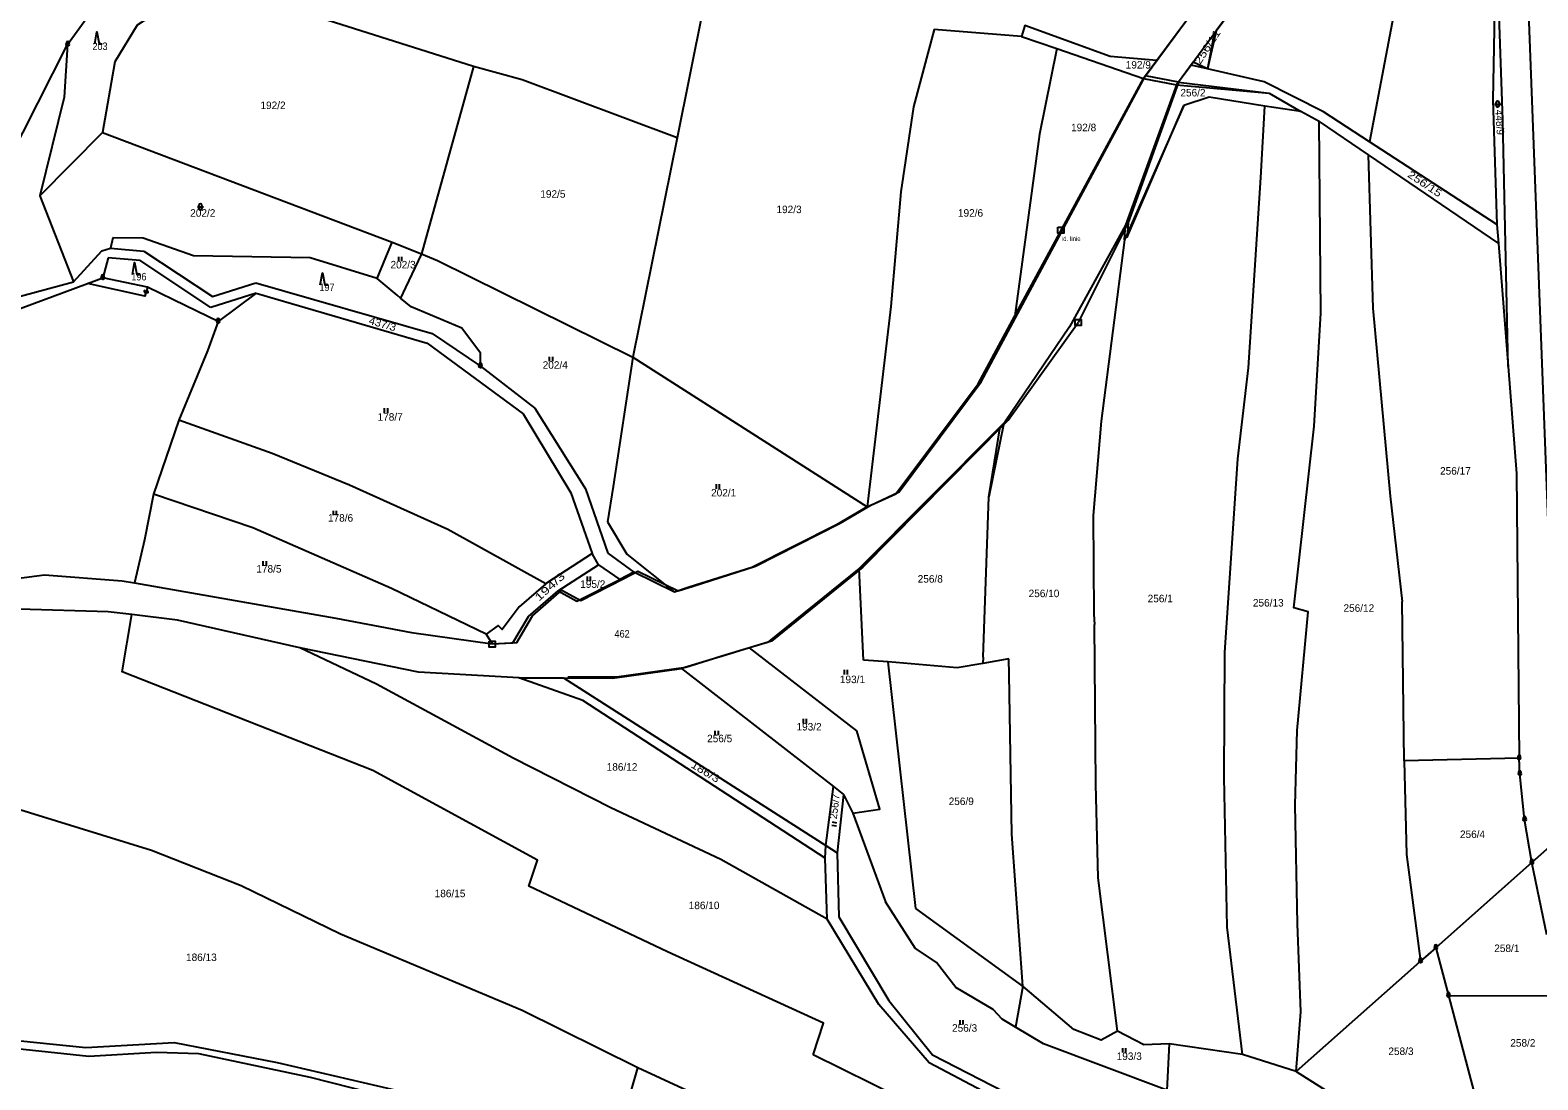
# Model space of a CAD drawing. Extents: x -680102 to -677253, y -1007548 to -1006096.
# Drawn here: x -678783 to -678281, y -1006966 to -1006617 of the extents above; entities that cross this region are included whole.
import ezdxf

# ---------------------------------------------------------------- set-up
doc = ezdxf.new("R2010")
doc.units = 0
for name, color, linetype, lineweight in [('1', 7, 'Continuous', 25), ('11', 7, 'Continuous', 25), ('24', 7, 'Continuous', 25), ('25', 7, 'Continuous', 25), ('35', 7, 'Continuous', 25), ('4', 7, 'Continuous', 25)]:
    doc.layers.add(name, color=color, linetype=linetype, lineweight=lineweight)
doc.layers.add('18', color=7, linetype='Continuous')

msp = doc.modelspace()

# ---------------------------------------------------------------- linework, layer by layer
at = {"layer": '1'}
for p, q in [((-678292.98, -1006647), (-678295.16, -1006581.68)), ((-678327.99, -1006605.23), (-678337.28, -1006654.25)), ((-678284.39, -1006611.4), (-678278.02, -1006780.4)), ((-678389.05, -1006618.29), (-678391.25, -1006629.93)), ((-678408.13, -1006627.15), (-678423.65, -1006625.83)), ((-678635.56, -1006629.14), (-678652.93, -1006691.54)), ((-678412.57, -1006633.12), (-678401.62, -1006635.25)), ((-678396.74, -1006628.67), (-678401.62, -1006635.25)), ((-678401.62, -1006635.25), (-678418.52, -1006681.96)), ((-678401.62, -1006635.25), (-678370.74, -1006638.02)), ((-678352.67, -1006644.27), (-678372.38, -1006634.27)), ((-678370.74, -1006638.02), (-678360.18, -1006644.19)), ((-678399.16, -1006642.13), (-678418.89, -1006686.84)), ((-678390.75, -1006639.42), (-678399.16, -1006642.13)), ((-678296.26, -1006640.29), (-678294.91, -1006681.72)), ((-678291.19, -1006729.01), (-678292.98, -1006647)), ((-678337.76, -1006658.53), (-678336.21, -1006709.63)), ((-678418.52, -1006681.96), (-678437.25, -1006715.74)), ((-678418.89, -1006686.84), (-678418.52, -1006681.96)), ((-678294.91, -1006681.72), (-678294.43, -1006688.11)), ((-678755.69, -1006686.13), (-678756.46, -1006689.57)), ((-678745.51, -1006686.29), (-678755.69, -1006686.13)), ((-678728.77, -1006692.22), (-678745.51, -1006686.29)), ((-678667.68, -1006699.66), (-678662.64, -1006687.58)), ((-678294.43, -1006688.11), (-678291.19, -1006729.01)), ((-678759.35, -1006690.53), (-678756.46, -1006689.57)), ((-678757.22, -1006692.78), (-678759.02, -1006699.49)), ((-678746.58, -1006693.69), (-678757.22, -1006692.78)), ((-678756.46, -1006689.57), (-678745.28, -1006690.57)), ((-678689.97, -1006692.83), (-678728.77, -1006692.22)), ((-678652.93, -1006691.54), (-678658.18, -1006702.66)), ((-678723.02, -1006709.32), (-678746.58, -1006693.69)), ((-678647.53, -1006693.75), (-678582.53, -1006725.83)), ((-678764.08, -1006701.41), (-678759.02, -1006699.49)), ((-678744.09, -1006702.62), (-678759.02, -1006699.49)), ((-678708.02, -1006701.1), (-678649.31, -1006718.06)), ((-678658.18, -1006702.66), (-678659.91, -1006706.22)), ((-678707.98, -1006704.58), (-678723.02, -1006709.32)), ((-678707.98, -1006704.58), (-678720.62, -1006714.05)), ((-678659.91, -1006706.22), (-678661.01, -1006705.29)), ((-678656.39, -1006709.18), (-678659.91, -1006706.22)), ((-678639.46, -1006716.2), (-678656.39, -1006709.18)), ((-678336.21, -1006709.63), (-678330.47, -1006772.13)), ((-678720.62, -1006714.05), (-678724.17, -1006723.76)), ((-678649.31, -1006718.06), (-678633.3, -1006728.9)), ((-678437.25, -1006715.74), (-678458.76, -1006747.53)), ((-678724.17, -1006723.76), (-678733.69, -1006746.86)), ((-678582.53, -1006725.83), (-678504.57, -1006775.64)), ((-678291.19, -1006729.01), (-678288.37, -1006764.62)), ((-678619.06, -1006744.74), (-678603.23, -1006770.99)), ((-678288.37, -1006764.62), (-678287.5, -1006859.31)), ((-678742.09, -1006771.5), (-678745.09, -1006786.69)), ((-678709.07, -1006782.71), (-678742.09, -1006771.5)), ((-678603.23, -1006770.99), (-678596.1, -1006791.26)), ((-678598.31, -1006769.67), (-678590.92, -1006791.09)), ((-678330.47, -1006772.13), (-678326.43, -1006807.17)), ((-678504.57, -1006775.64), (-678514.78, -1006781.69)), ((-678611.57, -1006801.32), (-678644.09, -1006783.19)), ((-678514.78, -1006781.69), (-678542.93, -1006795.87)), ((-678745.09, -1006786.69), (-678748.44, -1006800.99)), ((-678590.92, -1006791.09), (-678582.19, -1006797.41)), ((-678809.39, -1006802.43), (-678778.41, -1006798.31)), ((-678778.41, -1006798.31), (-678752.56, -1006800.28)), ((-678594.01, -1006794.95), (-678586.85, -1006799.87)), ((-678582.19, -1006797.41), (-678586.85, -1006799.87)), ((-678568.69, -1006804.03), (-678582.19, -1006797.41)), ((-678507.21, -1006796.26), (-678537.78, -1006820.79)), ((-678325.76, -1006860.25), (-678326.43, -1006807.17)), ((-678693.35, -1006822.57), (-678734.16, -1006813.39)), ((-678429.05, -1006811.35), (-678428.88, -1006814.85)), ((-678557.11, -1006826.67), (-678566.3, -1006829.46)), ((-678552.9, -1006825.39), (-678557.11, -1006826.67)), ((-678474.56, -1006829.3), (-678497.6, -1006827.29)), ((-678465.97, -1006825.71), (-678466.07, -1006827.77)), ((-678589.32, -1006832.67), (-678566.3, -1006829.46)), ((-678518.29, -1006888.42), (-678515.73, -1006868.76)), ((-678512.38, -1006871.37), (-678514.5, -1006890.81)), ((-678283.27, -1006894.09), (-678285.7, -1006879.74)), ((-678518.51, -1006892.56), (-678518.29, -1006888.42)), ((-678452.68, -1006935.19), (-678456.35, -1006884.57)), ((-678325.05, -1006891.38), (-678320.34, -1006926.92)), ((-678278.33, -1006918.05), (-678283.27, -1006894.09)), ((-678322.71, -1006929.01), (-678361.71, -1006963.54)), ((-678320.34, -1006926.92), (-678322.71, -1006929.01)), ((-678452.68, -1006935.19), (-678455.22, -1006948.82)), ((-678311.06, -1006938.3), (-678272.94, -1006938.41)), ((-678580.87, -1006962.32), (-678619.34, -1006943.25)), ((-678589.4, -1006991.58), (-678580.87, -1006962.32)), ((-678361.71, -1006963.54), (-678344.26, -1006974.65))]:
    msp.add_line(p, q, dxfattribs=at)
for points in [[(-678294.65, -1006573.35), (-678295.16, -1006581.68), (-678296.26, -1006640.29)], [(-678770.69, -1006621.83), (-678757.37, -1006603.24), (-678741.78, -1006591.66)], [(-678382.03, -1006592), (-678408.13, -1006627.15), (-678412.57, -1006633.12)], [(-678723.77, -1006599.91), (-678747.58, -1006615.43), (-678754.95, -1006627.57), (-678759.08, -1006651.17)], [(-678567.8, -1006652.87), (-678619.4, -1006633.56), (-678635.56, -1006629.14), (-678690.66, -1006611.71), (-678723.77, -1006599.91)], [(-678378.6, -1006604.2), (-678389.05, -1006618.29), (-678396.74, -1006628.67)], [(-678559.23, -1006610.41), (-678567.8, -1006652.87), (-678582.53, -1006725.83)], [(-678453.19, -1006619.16), (-678482.29, -1006616.83), (-678489.11, -1006642.57), (-678493.38, -1006670.87), (-678496.7, -1006709.02), (-678504.57, -1006775.64)], [(-678423.65, -1006625.83), (-678452.11, -1006615.47), (-678453.19, -1006619.16)], [(-678825.3, -1006702.25), (-678795.52, -1006670.55), (-678770.69, -1006621.83), (-678771.83, -1006639.32), (-678780, -1006672.18), (-678768.75, -1006700.87)], [(-678453.19, -1006619.16), (-678441.4, -1006623.21), (-678412.57, -1006633.12)], [(-678441.4, -1006623.21), (-678447.23, -1006651.72), (-678455.34, -1006712.11)], [(-678467.62, -1006734.78), (-678455.34, -1006712.11), (-678412.57, -1006633.12)], [(-678372.38, -1006634.27), (-678391.25, -1006629.93), (-678396.74, -1006628.67)], [(-678360.18, -1006644.19), (-678372.18, -1006642.32), (-678390.75, -1006639.42)], [(-678379.64, -1006957.94), (-678384.71, -1006915.5), (-678385.68, -1006865.59), (-678385.49, -1006824.2), (-678381.19, -1006759.69), (-678377.6, -1006729.48), (-678373.53, -1006666.09), (-678372.18, -1006642.32)], [(-678361.71, -1006963.54), (-678360.18, -1006943.72), (-678361.33, -1006914.42), (-678362.06, -1006874.92), (-678361.46, -1006850.06), (-678357.73, -1006810.61), (-678362.53, -1006809.3), (-678355.8, -1006748.81), (-678353.55, -1006711.22), (-678354.06, -1006647.41), (-678360.18, -1006644.19)], [(-678354.06, -1006647.41), (-678337.76, -1006658.53), (-678294.43, -1006688.11)], [(-678294.91, -1006681.72), (-678337.28, -1006654.25), (-678352.67, -1006644.27)], [(-678780, -1006672.18), (-678759.08, -1006651.17), (-678662.64, -1006687.58)], [(-678662.64, -1006687.58), (-678652.93, -1006691.54), (-678647.53, -1006693.75)], [(-678418.89, -1006686.84), (-678426.68, -1006747.13), (-678429.29, -1006778.6), (-678429.05, -1006811.35)], [(-678830.07, -1006706.12), (-678825.3, -1006702.25), (-678804.17, -1006710.32), (-678768.75, -1006700.87), (-678759.35, -1006690.53)], [(-678745.28, -1006690.57), (-678722.52, -1006705.7), (-678708.02, -1006701.1)], [(-678661.01, -1006705.29), (-678667.68, -1006699.66), (-678689.97, -1006692.83)], [(-678801.5, -1006712.47), (-678790.35, -1006711.15), (-678764.08, -1006701.41)], [(-678720.62, -1006714.05), (-678731.31, -1006708.84), (-678744.09, -1006702.62)], [(-678707.98, -1006704.58), (-678651.04, -1006721.27), (-678619.06, -1006744.74)], [(-678633.3, -1006728.9), (-678633.27, -1006724.57), (-678639.46, -1006716.2)], [(-678582.53, -1006725.83), (-678589.14, -1006768.88), (-678590.95, -1006780.65)], [(-678633.3, -1006728.9), (-678615.21, -1006742.84), (-678598.31, -1006769.67)], [(-678504.57, -1006775.64), (-678495.02, -1006771.31), (-678467.62, -1006734.78)], [(-678702.61, -1006757.93), (-678733.69, -1006746.86), (-678742.09, -1006771.5)], [(-678458.76, -1006747.53), (-678460.31, -1006749.09), (-678507.21, -1006796.26)], [(-678465.97, -1006825.71), (-678464.06, -1006772.32), (-678460.31, -1006749.09)], [(-678644.09, -1006783.19), (-678676.91, -1006768.49), (-678702.61, -1006757.93)], [(-678631.41, -1006818.02), (-678662.94, -1006802.85), (-678709.07, -1006782.71)], [(-678590.95, -1006780.65), (-678584.59, -1006791.47), (-678568.69, -1006804.03)], [(-678681.43, -1006812.76), (-678656.18, -1006817.5), (-678629.37, -1006821.24), (-678622.5, -1006820.98), (-678617.29, -1006812.19), (-678607.46, -1006803.61), (-678594.01, -1006794.95), (-678596.1, -1006791.26), (-678611.34, -1006801.12)], [(-678542.93, -1006795.87), (-678563.77, -1006802.47), (-678568.69, -1006804.03)], [(-678505.82, -1006826.67), (-678506.03, -1006822.05), (-678507.21, -1006796.26)], [(-678752.56, -1006800.28), (-678748.44, -1006800.99), (-678681.43, -1006812.76)], [(-678611.34, -1006801.12), (-678611.57, -1006801.32), (-678620.34, -1006808.98)], [(-678607.46, -1006803.61), (-678601.18, -1006807.05), (-678586.85, -1006799.87)], [(-678757.2, -1006810.62), (-678786.87, -1006809.74), (-678808.33, -1006812.25), (-678855.42, -1006828.22), (-678875.46, -1006840.19)], [(-678734.16, -1006813.39), (-678749.38, -1006811.56), (-678757.2, -1006810.62)], [(-678570.97, -1006923.78), (-678617.18, -1006901.88), (-678614.3, -1006893.22), (-678669.14, -1006863.38), (-678752.57, -1006830.6), (-678749.38, -1006811.56)], [(-678620.34, -1006808.98), (-678626.07, -1006816.55), (-678627.33, -1006815.14), (-678631.41, -1006818.02), (-678629.37, -1006821.24)], [(-678421.24, -1006950.19), (-678427.67, -1006899.18), (-678428.43, -1006867.92), (-678428.88, -1006814.85)], [(-678517.9, -1006912.86), (-678553.21, -1006893.09), (-678589.86, -1006875.88), (-678622.42, -1006859.28), (-678667.88, -1006834.7), (-678693.35, -1006822.57)], [(-678620.49, -1006832.57), (-678653.9, -1006830.72), (-678693.35, -1006822.57)], [(-678537.78, -1006820.79), (-678543.67, -1006822.58), (-678552.9, -1006825.39)], [(-678509.3, -1006877.66), (-678500.3, -1006876.27), (-678507.96, -1006850.17), (-678543.67, -1006822.58)], [(-678488.35, -1006909.3), (-678497.6, -1006827.29), (-678505.82, -1006826.67)], [(-678457.4, -1006826.21), (-678466.07, -1006827.77), (-678474.56, -1006829.3)], [(-678456.35, -1006884.57), (-678457.31, -1006831.43), (-678457.4, -1006826.21)], [(-678398.33, -1007005.38), (-678440.63, -1006983.55), (-678483.96, -1006960.65), (-678500.63, -1006941.25), (-678517.9, -1006912.86), (-678518.51, -1006892.56), (-678599.19, -1006840.09), (-678620.49, -1006832.57)], [(-678620.49, -1006832.57), (-678605.61, -1006832.62), (-678589.32, -1006832.67)], [(-678605.61, -1006832.62), (-678518.29, -1006888.42), (-678514.5, -1006890.81), (-678513.99, -1006912.1), (-678497.38, -1006940)], [(-678566.3, -1006829.46), (-678515.73, -1006868.76), (-678512.38, -1006871.37)], [(-678285.7, -1006879.74), (-678287.32, -1006864.53), (-678287.5, -1006859.31), (-678325.76, -1006860.25), (-678325.05, -1006891.38)], [(-678619.34, -1006943.25), (-678679.89, -1006917.85), (-678712.96, -1006901.76), (-678742.78, -1006890), (-678790.92, -1006875.17), (-678826.88, -1006865.18)], [(-678512.38, -1006871.37), (-678509.3, -1006877.66), (-678498.46, -1006907.11)], [(-678283.27, -1006894.09), (-678315.26, -1006922.42), (-678320.34, -1006926.92)], [(-678459.57, -1006946.2), (-678462.59, -1006942.93), (-678475.05, -1006935.68), (-678481.46, -1006927.33), (-678488.59, -1006922.49), (-678498.46, -1006907.11)], [(-678361.71, -1006963.54), (-678379.64, -1006957.94), (-678404.06, -1006954.43), (-678412.41, -1006954.67), (-678421.24, -1006950.19), (-678426.68, -1006953.1), (-678435.75, -1006949.59), (-678452.68, -1006935.19), (-678488.35, -1006909.3)], [(-678522.49, -1006958), (-678519.05, -1006947.54), (-678570.97, -1006923.78)], [(-678315.26, -1006922.42), (-678311.06, -1006938.3), (-678302.61, -1006970.19), (-678264.49, -1006970.3)], [(-678497.38, -1006940), (-678482.78, -1006958), (-678407.48, -1006996.76)], [(-678445.9, -1006954.43), (-678455.22, -1006948.82), (-678459.57, -1006946.2)], [(-678741.11, -1006957.27), (-678763.59, -1006958.64), (-678796.05, -1006955.12), (-678818.04, -1006953.75), (-678852.96, -1006954.87)], [(-678821.5, -1006950.78), (-678786.36, -1006953.33), (-678764.64, -1006955.64)], [(-678764.64, -1006955.64), (-678735.18, -1006953.98), (-678700.9, -1006960.54)], [(-678428.42, -1007058.52), (-678456.65, -1007048.79), (-678480.7, -1007039.81), (-678505.2, -1007028.21), (-678600.16, -1006990.16), (-678648.38, -1006976.17), (-678689.83, -1006965.56), (-678727.06, -1006957.66), (-678741.11, -1006957.27)], [(-678448.47, -1006998.31), (-678464.79, -1006989.56), (-678493.35, -1006972.45), (-678522.49, -1006958)], [(-678404.06, -1006954.43), (-678404.79, -1006969.79), (-678445.9, -1006954.43)], [(-678700.9, -1006960.54), (-678658.05, -1006970.53), (-678610.61, -1006983.2)], [(-678404.4, -1007041.11), (-678426.05, -1007034.58), (-678466.45, -1007018.51), (-678510.07, -1006995.35), (-678525.91, -1006987.79), (-678580.87, -1006962.32)]]:
    msp.add_lwpolyline(points, dxfattribs=at)
at = {"layer": '11'}
for p, q in [((-678400.89, -1006634.35), (-678370.74, -1006638.02)), ((-678417.64, -1006681.12), (-678434.3, -1006714.32)), ((-678457.66, -1006746.82), (-678434.3, -1006714.32))]:
    msp.add_line(p, q, dxfattribs=at)
for points in [[(-678282.9, -1006501.51), (-678288.96, -1006531.28), (-678290.92, -1006545.55), (-678299.42, -1006535.34), (-678316.02, -1006548.44), (-678337.35, -1006565.27), (-678377.98, -1006603.23), (-678388.38, -1006617.35), (-678391.25, -1006629.93), (-678396.04, -1006627.76), (-678400.89, -1006634.35), (-678411.85, -1006632.26)], [(-678629.37, -1006821.24), (-678621.16, -1006820.81), (-678615.98, -1006812), (-678606.18, -1006803.39), (-678599.89, -1006806.81), (-678585.58, -1006799.58), (-678580.93, -1006797.11), (-678567.41, -1006803.68), (-678562.49, -1006802.11), (-678541.67, -1006795.44), (-678513.57, -1006781.17), (-678503.38, -1006775.08), (-678493.85, -1006770.72), (-678466.57, -1006734.1), (-678454.36, -1006711.39), (-678411.85, -1006632.26), (-678407.43, -1006626.27), (-678381.45, -1006591.04), (-678371.57, -1006577.31), (-678346.7, -1006550.29), (-678328.04, -1006532.61), (-678313.38, -1006521.44), (-678323.91, -1006515.59)], [(-678400.89, -1006634.35), (-678417.64, -1006681.12), (-678417.99, -1006686), (-678399.16, -1006642.13)], [(-678459.21, -1006748.39), (-678505.95, -1006795.71), (-678536.44, -1006820.34), (-678542.33, -1006822.15), (-678551.55, -1006824.99), (-678555.75, -1006826.28), (-678564.93, -1006829.1), (-678587.94, -1006832.39), (-678604.23, -1006832.39)], [(-678457.66, -1006746.82), (-678459.21, -1006748.39), (-678464.06, -1006772.32)]]:
    msp.add_lwpolyline(points, dxfattribs=at)
at = {"layer": '24'}
for centre, radius in [((-678770.69, -1006621.83), 0.5), ((-678770.69, -1006621.83), 0.022), ((-678759.02, -1006699.49), 0.5), ((-678759.02, -1006699.49), 0.022), ((-678720.62, -1006714.05), 0.5), ((-678720.62, -1006714.05), 0.022), ((-678633.3, -1006728.9), 0.5), ((-678633.3, -1006728.9), 0.022), ((-678287.5, -1006859.31), 0.5), ((-678287.5, -1006859.31), 0.022), ((-678287.32, -1006864.53), 0.5), ((-678287.32, -1006864.53), 0.022), ((-678285.7, -1006879.74), 0.5), ((-678285.7, -1006879.74), 0.022), ((-678283.27, -1006894.09), 0.5), ((-678283.27, -1006894.09), 0.022), ((-678315.26, -1006922.42), 0.5), ((-678315.26, -1006922.42), 0.022), ((-678320.34, -1006926.92), 0.5), ((-678320.34, -1006926.92), 0.022), ((-678311.06, -1006938.3), 0.5), ((-678311.06, -1006938.3), 0.022)]:
    msp.add_circle(centre, radius, dxfattribs=at)
for centre in [(-678770.691, -1006621.267), (-678759.021, -1006698.927), (-678720.621, -1006713.487), (-678633.301, -1006728.337), (-678287.501, -1006858.747), (-678287.321, -1006863.967), (-678285.701, -1006879.177), (-678283.271, -1006893.527), (-678315.261, -1006921.857), (-678320.341, -1006926.357), (-678311.061, -1006937.737)]:
    msp.add_arc(centre, 0.437, 328.35109, 209.97456, dxfattribs=at)
at = {"layer": '25'}
for p, q in [((-678295.67, -1006641.66), (-678293.67, -1006641.66)), ((-678295.17, -1006642.16), (-678295.17, -1006641.16)), ((-678294.17, -1006641.16), (-678294.17, -1006642.16)), ((-678727.52, -1006675.87), (-678725.52, -1006675.87)), ((-678727.02, -1006676.37), (-678727.02, -1006675.37)), ((-678726.02, -1006675.37), (-678726.02, -1006676.37)), ((-678660.467, -1006693.975), (-678660.467, -1006692.475)), ((-678659.433, -1006693.975), (-678659.433, -1006692.475)), ((-678610.247, -1006727.265), (-678610.247, -1006725.765)), ((-678609.213, -1006727.265), (-678609.213, -1006725.765)), ((-678665.167, -1006744.375), (-678665.167, -1006742.875)), ((-678664.133, -1006744.375), (-678664.133, -1006742.875)), ((-678554.707, -1006769.695), (-678554.707, -1006768.195)), ((-678553.673, -1006769.695), (-678553.673, -1006768.195)), ((-678682.217, -1006778.475), (-678682.217, -1006776.975)), ((-678681.183, -1006778.475), (-678681.183, -1006776.975)), ((-678705.567, -1006795.275), (-678705.567, -1006793.775)), ((-678704.533, -1006795.275), (-678704.533, -1006793.775)), ((-678597.697, -1006800.405), (-678597.697, -1006798.905)), ((-678596.663, -1006800.405), (-678596.663, -1006798.905)), ((-678512.097, -1006831.475), (-678512.097, -1006829.975)), ((-678511.063, -1006831.475), (-678511.063, -1006829.975)), ((-678525.797, -1006847.735), (-678525.797, -1006846.235)), ((-678524.763, -1006847.735), (-678524.763, -1006846.235)), ((-678555.097, -1006851.695), (-678555.097, -1006850.195)), ((-678554.063, -1006851.695), (-678554.063, -1006850.195)), ((-678514.807, -1006881.92), (-678516.286, -1006881.67)), ((-678514.635, -1006880.902), (-678516.114, -1006880.651)), ((-678473.587, -1006947.955), (-678473.587, -1006946.455)), ((-678472.553, -1006947.955), (-678472.553, -1006946.455)), ((-678419.487, -1006957.285), (-678419.487, -1006955.785)), ((-678418.453, -1006957.285), (-678418.453, -1006955.785))]:
    msp.add_line(p, q, dxfattribs=at)
for points in [[(-678761.69, -1006621.58), (-678760.94, -1006617.58), (-678760.19, -1006621.58), (-678759.19, -1006621.58)], [(-678749.15, -1006698.43), (-678748.4, -1006694.43), (-678747.65, -1006698.43), (-678746.65, -1006698.43)], [(-678686.6, -1006701.84), (-678685.85, -1006697.84), (-678685.1, -1006701.84), (-678684.1, -1006701.84)]]:
    msp.add_lwpolyline(points, dxfattribs=at)
for centre, radius, start, end in [((-678294.67, -1006641.16), 0.5, 0.101, 180.00143), ((-678294.67, -1006642.16), 0.5, 180.10243, 0.00286), ((-678726.52, -1006675.37), 0.5, 0.101, 180.00143), ((-678726.52, -1006676.37), 0.5, 180.10243, 0.00286), ((-678744.901, -1006703.966), 0.369, 110.01057, 341.81548), ((-678744.2, -1006704.192), 0.367, 289.89097, 162.25662)]:
    msp.add_arc(centre, radius, start, end, dxfattribs=at)
at = {"layer": '35'}
for points in [[(-678441.06, -1006682.64), (-678439.06, -1006682.64), (-678439.06, -1006684.64), (-678441.06, -1006684.64)], [(-678435.3, -1006713.32), (-678433.3, -1006713.32), (-678433.3, -1006715.32), (-678435.3, -1006715.32)], [(-678630.38, -1006820.36), (-678628.38, -1006820.36), (-678628.38, -1006822.36), (-678630.38, -1006822.36)]]:
    msp.add_lwpolyline(points, close=True, dxfattribs=at)
at = {"layer": '4'}
msp.add_line((-678283.27, -1006894.09), (-678274.13, -1006885.85), dxfattribs=at)
msp.add_lwpolyline([(-678744.09, -1006702.62), (-678745, -1006705.54), (-678764.08, -1006701.41)], dxfattribs=at)

# ---------------------------------------------------------------- texts
at = {"layer": '18'}
for s, rotation, width, p in [('256/11', 57.2, 1.25, (-678393.679, -1006628.654)), ('256/15', 326.303, 1.25, (-678324.923, -1006665.705)), ('437/3', 343.903, 1.1, (-678670.643, -1006714.764)), ('194/3', 42.5, 1.45, (-678613.818, -1006807.278)), ('186/3', 328.803, 1.25, (-678563.486, -1006862.193))]:
    msp.add_text(s, height=2.5, rotation=rotation, dxfattribs=dict(at, width=width)).set_placement(p)
at = {"layer": '18', "width": 0.9}
for s, p in [('203', (-678762.43, -1006623.68)), ('196', (-678749.47, -1006700.35)), ('197', (-678686.88, -1006703.88)), ('462', (-678588.63, -1006819.18))]:
    msp.add_text(s, height=2.5, dxfattribs=at).set_placement(p)
at = {"layer": '18'}
for s, p in [('192/9', (-678418.48, -1006629.85)), ('256/2', (-678400.28, -1006639.12)), ('192/2', (-678706.51, -1006643.33)), ('192/8', (-678436.67, -1006650.7)), ('192/5', (-678613.35, -1006672.83)), ('202/2', (-678729.89, -1006679.15)), ('192/3', (-678534.74, -1006677.96)), ('192/6', (-678474.33, -1006679.13)), ('202/3', (-678663.22, -1006696.35)), ('202/4', (-678612.57, -1006729.74)), ('178/7', (-678667.53, -1006747.03)), ('256/17', (-678313.84, -1006764.97)), ('202/1', (-678556.5, -1006772.23)), ('178/6', (-678684.03, -1006780.61)), ('178/5', (-678707.88, -1006797.57)), ('256/8', (-678487.73, -1006800.91)), ('195/2', (-678600.07, -1006802.64)), ('256/10', (-678450.8, -1006805.74)), ('256/1', (-678411.18, -1006807.44)), ('256/13', (-678376.14, -1006808.86)), ('256/12', (-678345.99, -1006810.61)), ('193/1', (-678513.64, -1006834.35)), ('193/2', (-678528.07, -1006850.11)), ('256/5', (-678557.83, -1006854.02)), ('186/12', (-678591.26, -1006863.48)), ('256/9', (-678477.42, -1006874.92)), ('256/4', (-678307.22, -1006885.89)), ('186/15', (-678648.52, -1006905.59)), ('186/10', (-678563.95, -1006909.56)), ('186/13', (-678731.28, -1006926.83)), ('258/1', (-678295.81, -1006923.83)), ('256/3', (-678476.3, -1006950.35)), ('258/2', (-678290.47, -1006955.31)), ('193/3', (-678421.49, -1006959.75)), ('258/3', (-678331.04, -1006958.1))]:
    msp.add_text(s, height=2.5, dxfattribs=at).set_placement(p)
for s, rotation, p in [('448/9', 273.602, (-678295.478, -1006643.637)), ('256/7', 83.001, (-678514.674, -1006879.698))]:
    msp.add_text(s, height=2.5, rotation=rotation, dxfattribs=at).set_placement(p)
at = {"layer": '35', "width": 0.8}
msp.add_text('id. linie', height=1.5, dxfattribs=at).set_placement((-678439.74, -1006687.21))

doc.saveas('drawing.dxf')
